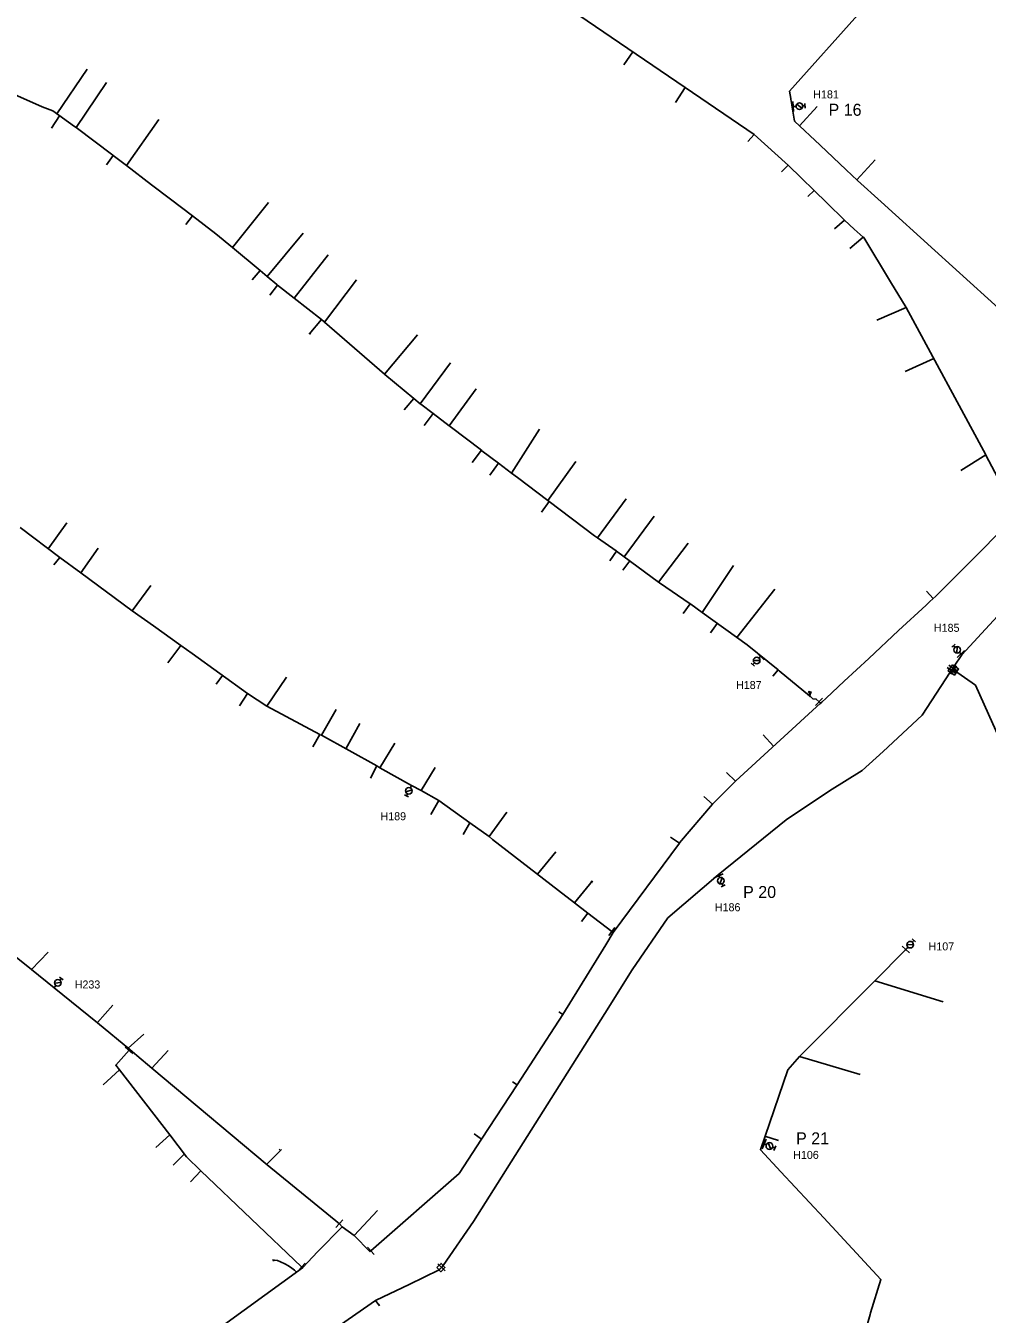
# Model space of a CAD drawing. Extents: x -548873 to -538270, y -1201997 to -1192514.
# Drawn here: x -544704.3 to -544463.9, y -1193277.9 to -1192955.8 of the extents above; entities that cross this region are included whole.
import ezdxf

# ---------------------------------------------------------------- set-up
doc = ezdxf.new("R2010")
doc.units = 0
for name, color, linetype in [('KN_HRAN_STÁTNÍ', 7, 'Continuous'), ('KN_PARC_Č', 7, 'Continuous'), ('KN_VKP_HRAN_SPORNÁ', 7, 'Continuous'), ('PK_PARC_Čv', 7, 'Continuous'), ('Vrstva 29', 7, 'Continuous'), ('Vrstva 39', 7, 'Continuous')]:
    doc.layers.add(name, color=color, linetype=linetype)

# ---------------------------------------------------------------- blocks, each defined once
blk = doc.blocks.new('160')
at = {"layer": 'KN_HRAN_STÁTNÍ'}
blk.add_circle((0, 0), 0.0458, dxfattribs=at)
blk = doc.blocks.new('147')
at = {"layer": 'KN_HRAN_STÁTNÍ'}
blk.add_line((0, 1.27), (0, -1.27), dxfattribs=at)
blk = doc.blocks.new('133')
at = {"layer": 'KN_HRAN_STÁTNÍ'}
for p, q in [((0.28, 0), (0, 0)), ((0.54, 0.58), (1.7, -0.58)), ((1.94, 0), (2.52, 0)), ((2.52, 0.58), (2.52, -0.58))]:
    blk.add_line(p, q, dxfattribs=at)
blk.add_circle((1.11, 0), 0.825, dxfattribs=at)
blk = doc.blocks.new('150')
at = {"layer": 'KN_HRAN_STÁTNÍ'}
blk.add_line((0, 1.27), (0, -1.27), dxfattribs=at)
blk = doc.blocks.new('128')
at = {"layer": 'KN_HRAN_STÁTNÍ'}
for p, q in [((-0.19, 1.06), (-0.43, 1.15)), ((-0.36, 0.84), (-0.19, 1.06)), ((-0.19, 1.06), (-0.02, 1.25)), ((-0.19, 1.06), (0, 0)), ((0.05, 0.95), (-0.19, 1.06)), ((-0.1, 1), (0.41, 0.91)), ((-0.07, 0.82), (0.17, 0.96)), ((0.17, 0.96), (-0.02, 1.13)), ((0.17, 0.96), (0, 0)), ((0.19, 1.21), (0.17, 0.96)), ((0.17, 0.96), (0.38, 1.08)), ((0.36, 0.77), (0.17, 0.96))]:
    blk.add_line(p, q, dxfattribs=at)

msp = doc.modelspace()

# ---------------------------------------------------------------- linework, layer by layer
at = {"layer": 'KN_PARC_Č'}
for points in [[(-544552.563, -1192962.313), (-544554.747, -1192965.528)], [(-544696.557, -1192977.763), (-544688.945, -1192966.668)], [(-544691.743, -1192981.23), (-544684.158, -1192969.979)], [(-544539.413, -1192971.242), (-544541.838, -1192974.939)], [(-544510.834, -1192980.776), (-544506.437, -1192975.971)], [(-544695.852, -1192978.269), (-544697.877, -1192981.372)], [(-544679.159, -1192990.721), (-544671.055, -1192979.195)], [(-544522.184, -1192982.942), (-544523.759, -1192984.755)], [(-544682.451, -1192988.202), (-544684.101, -1192990.568)], [(-544513.715, -1192990.627), (-544515.313, -1192992.312)], [(-544496.492, -1192994.312), (-544491.896, -1192989.278)], [(-544507.167, -1192997.006), (-544508.734, -1192998.469)], [(-544652.623, -1193011.242), (-544643.629, -1192999.931)], [(-544662.648, -1193003.313), (-544664.279, -1193005.439)], [(-544499.576, -1193004.409), (-544502.123, -1193006.532)], [(-544643.97, -1193018.447), (-544634.949, -1193007.651)], [(-544494.915, -1193008.609), (-544498.254, -1193011.44)], [(-544637.186, -1193023.891), (-544628.666, -1193013.022)], [(-544645.731, -1193016.98), (-544647.729, -1193019.337)], [(-544641.352, -1193020.618), (-544643.28, -1193023.111)], [(-544629.585, -1193029.871), (-544621.659, -1193019.321)], [(-544484.158, -1193026.242), (-544491.515, -1193029.421)], [(-544630.393, -1193029.228), (-544633.485, -1193032.887)], [(-544633.288, -1193032.654), (-544633.032, -1193032.902)], [(-544614.612, -1193042.888), (-544606.346, -1193033.069)], [(-544605.671, -1193050.288), (-544598.083, -1193040.009)], [(-544477.297, -1193038.937), (-544484.393, -1193042.193)], [(-544598.47, -1193055.78), (-544591.723, -1193046.565)], [(-544607.286, -1193048.952), (-544609.698, -1193051.761)], [(-544602.449, -1193052.749), (-544604.682, -1193055.69)], [(-544582.838, -1193067.588), (-544575.843, -1193056.6)], [(-544590.372, -1193061.918), (-544592.702, -1193064.947)], [(-544464.277, -1193063.025), (-544470.496, -1193066.929)], [(-544586.126, -1193065.113), (-544588.276, -1193068.114)], [(-544573.78, -1193074.441), (-544566.778, -1193064.72)], [(-544573.425, -1193074.71), (-544575.367, -1193077.389)], [(-544561.39, -1193083.781), (-544554.189, -1193074.057)], [(-544554.668, -1193088.533), (-544547.159, -1193078.388)], [(-544698.699, -1193086.56), (-544694.063, -1193080.04)], [(-544546.072, -1193094.881), (-544538.716, -1193085.135)], [(-544695.835, -1193088.729), (-544697.309, -1193090.56)], [(-544690.58, -1193092.58), (-544686.181, -1193086.351)], [(-544556.59, -1193087.113), (-544558.311, -1193089.543)], [(-544553.281, -1193089.557), (-544554.982, -1193091.91)], [(-544535.197, -1193102.446), (-544527.365, -1193090.684)], [(-544677.716, -1193102.007), (-544673.08, -1193095.702)], [(-544526.48, -1193108.739), (-544517.008, -1193096.655)], [(-544477.419, -1193098.937), (-544479.091, -1193097.135)], [(-544538.191, -1193100.29), (-544539.897, -1193102.69)], [(-544531.41, -1193105.18), (-544533.126, -1193107.544)], [(-544665.535, -1193110.695), (-544668.8, -1193115.028)], [(-544516.187, -1193116.808), (-544517.478, -1193118.393)], [(-544655.161, -1193118.17), (-544656.72, -1193120.413)], [(-544644.007, -1193125.875), (-544639.156, -1193118.593)], [(-544648.905, -1193122.676), (-544650.905, -1193125.814)], [(-544630.399, -1193133.154), (-544626.709, -1193126.717)], [(-544624.292, -1193136.532), (-544620.774, -1193130.171)], [(-544630.805, -1193132.932), (-544632.56, -1193136.071)], [(-544517.327, -1193135.896), (-544519.926, -1193133.051)], [(-544615.759, -1193141.252), (-544612.068, -1193135.091)], [(-544616.531, -1193140.825), (-544618.139, -1193143.839)], [(-544605.46, -1193146.987), (-544601.931, -1193141.209)], [(-544526.877, -1193144.631), (-544529.128, -1193142.424)], [(-544601.063, -1193149.437), (-544603.031, -1193152.984)], [(-544532.605, -1193150.374), (-544534.738, -1193148.484)], [(-544588.485, -1193158.492), (-544583.991, -1193152.368)], [(-544593.281, -1193155.037), (-544594.973, -1193157.975)], [(-544540.888, -1193160.119), (-544543.087, -1193158.62)], [(-544576.397, -1193167.831), (-544571.814, -1193162.282)], [(-544567.093, -1193175.016), (-544562.635, -1193169.556)], [(-544562.825, -1193169.788), (-544563.058, -1193169.6)], [(-544562.825, -1193169.788), (-544562.582, -1193169.964)], [(-544563.754, -1193177.595), (-544565.364, -1193179.732)], [(-544702.914, -1193191.718), (-544698.68, -1193187.35)], [(-544492.02, -1193194.514), (-544474.9, -1193199.779)], [(-544686.37, -1193204.994), (-544682.51, -1193200.6)], [(-544570.016, -1193202.943), (-544571.008, -1193202.272)], [(-544678.732, -1193211.393), (-544674.78, -1193207.83)], [(-544672.785, -1193216.375), (-544668.708, -1193211.976)], [(-544510.838, -1193213.431), (-544495.705, -1193217.946)], [(-544680.913, -1193216.779), (-544684.994, -1193220.504)], [(-544581.478, -1193220.511), (-544582.628, -1193219.787)], [(-544668.284, -1193233.013), (-544671.824, -1193236.195)], [(-544590.357, -1193234.131), (-544592.203, -1193232.784)], [(-544519.479, -1193233.391), (-544516.062, -1193234.492)], [(-544644.095, -1193240.409), (-544640.335, -1193236.721)], [(-544640.609, -1193236.99), (-544640.969, -1193236.58)], [(-544664.684, -1193237.838), (-544667.42, -1193240.634)], [(-544660.554, -1193241.995), (-544663.146, -1193244.767)], [(-544622.24, -1193258.16), (-544616.386, -1193251.924)], [(-544636.617, -1193267.35), (-544637.133, -1193266.878), (-544637.781, -1193266.336), (-544638.635, -1193265.787), (-544639.514, -1193265.268), (-544640.639, -1193264.742), (-544641.393, -1193264.484), (-544642.187, -1193264.325), (-544642.641, -1193264.278)], [(-544642.343, -1193264.309), (-544642.381, -1193264.607)], [(-544616.853, -1193274.488), (-544615.894, -1193275.746)], [(-544616.076, -1193275.507), (-544615.836, -1193275.327)]]:
    msp.add_lwpolyline(points, dxfattribs=at)
at = {"layer": 'KN_VKP_HRAN_SPORNÁ'}
for points in [[(-544560.275, -1192940.72), (-544559.97, -1192940.35), (-544557.033, -1192936.489), (-544556.428, -1192935.692), (-544545.966, -1192923.41), (-544534.516, -1192909.967), (-544533.273, -1192908.508), (-544530.926, -1192907.242), (-544528.833, -1192909.155), (-544521.348, -1192915.993), (-544512.949, -1192923.667), (-544498.441, -1192936.942), (-544491.038, -1192943.716), (-544490.115, -1192946.195), (-544495.563, -1192952.279), (-544513.363, -1192972.156), (-544513.04, -1192974.001), (-544513.001, -1192974.228), (-544512.946, -1192974.544), (-544512.868, -1192974.987), (-544512.752, -1192975.65), (-544512.058, -1192979.621)], [(-544456.83, -1193077.14), (-544464.218, -1193063.134), (-544464.277, -1193063.026), (-544484.158, -1193026.242), (-544488.072, -1193019.795), (-544494.802, -1193008.711), (-544494.915, -1193008.609), (-544497.144, -1193006.604), (-544499.581, -1193004.404), (-544504.015, -1193000.08), (-544513.635, -1192990.699), (-544522.182, -1192982.943), (-544539.415, -1192971.241), (-544566.053, -1192953.153), (-544568.615, -1192951.413)], [(-544508.241, -1193123.394), (-544508.346, -1193123.307), (-544515.91, -1193117.03), (-544516.187, -1193116.808), (-544523.93, -1193110.58), (-544535.197, -1193102.446), (-544538.06, -1193100.38), (-544538.191, -1193100.29), (-544545.83, -1193095.06), (-544546.072, -1193094.881), (-544556.59, -1193087.113), (-544556.73, -1193087.01), (-544561.39, -1193083.781), (-544562.07, -1193083.31), (-544573.425, -1193074.71), (-544573.78, -1193074.441), (-544581.36, -1193068.7), (-544582.838, -1193067.588), (-544586.126, -1193065.113), (-544590.25, -1193062.01), (-544590.372, -1193061.918), (-544598.221, -1193055.969), (-544598.47, -1193055.78), (-544602.449, -1193052.749), (-544605.56, -1193050.38), (-544605.671, -1193050.288), (-544607.286, -1193048.952), (-544614.54, -1193042.95), (-544614.628, -1193042.874), (-544629.585, -1193029.871), (-544629.689, -1193029.781), (-544630.393, -1193029.228), (-544637.186, -1193023.891), (-544641.352, -1193020.618), (-544641.541, -1193020.469), (-544643.97, -1193018.447), (-544645.731, -1193016.98), (-544652.623, -1193011.242), (-544656.794, -1193007.769), (-544662.648, -1193003.313), (-544668.152, -1192999.122), (-544672.87, -1192995.53), (-544679.159, -1192990.721), (-544682.451, -1192988.202), (-544682.52, -1192988.15), (-544691.743, -1192981.23), (-544692.13, -1192980.94), (-544697.55, -1192977.05), (-544700.25, -1192976.03), (-544709.386, -1192971.951)], [(-544439.522, -1193045.855), (-544447.584, -1193038.561), (-544454.922, -1193031.924), (-544476.979, -1193011.971), (-544490.412, -1192999.819), (-544496.321, -1192994.473), (-544499.196, -1192991.767), (-544505.659, -1192985.663), (-544512.058, -1192979.621)], [(-544422.078, -1193064.345), (-544430.27, -1193071.99), (-544441.63, -1193082.23), (-544453.43, -1193094.81), (-544470.28, -1193113.04), (-544472.153, -1193115.863), (-544472.455, -1193116.306)], [(-544456.45, -1193078.116), (-544462.553, -1193084.168), (-544464.285, -1193085.892), (-544471.685, -1193093.259), (-544475.202, -1193096.76), (-544476.79, -1193098.341), (-544478.25, -1193099.724), (-544479.197, -1193100.606), (-544486.066, -1193107.001), (-544493.541, -1193113.959), (-544499.639, -1193119.637), (-544504.217, -1193123.898), (-544505.249, -1193124.859), (-544505.577, -1193125.164)], [(-544705.725, -1193081.237), (-544695.839, -1193088.726), (-544690.581, -1193092.579), (-544677.721, -1193102.003), (-544672.419, -1193105.785), (-544665.535, -1193110.695), (-544662.739, -1193112.71), (-544648.907, -1193122.675), (-544644.007, -1193125.875), (-544630.805, -1193132.932), (-544630.668, -1193133.005), (-544630.399, -1193133.154), (-544616.529, -1193140.826), (-544615.761, -1193141.251), (-544607.831, -1193145.667), (-544605.462, -1193146.987), (-544601.063, -1193149.437), (-544601.015, -1193149.463), (-544593.281, -1193155.037), (-544588.481, -1193158.495), (-544587.585, -1193159.187), (-544571.081, -1193171.939), (-544567.093, -1193175.016), (-544563.755, -1193177.594), (-544557.758, -1193182.227)], [(-544472.889, -1193116.942), (-544473.188, -1193117.38), (-544480.16, -1193128.16), (-544489.91, -1193137.19), (-544495.19, -1193141.96), (-544503.33, -1193147.04), (-544514.15, -1193154.28), (-544531.2, -1193168.08), (-544543.76, -1193178.79), (-544552.71, -1193191.79), (-544559.541, -1193202.681), (-544592.365, -1193254.676), (-544599.934, -1193265.732), (-544600.353, -1193266.159)], [(-544472.647, -1193116.587), (-544472.889, -1193116.942)], [(-544472.455, -1193116.306), (-544472.647, -1193116.587)], [(-544472.647, -1193116.587), (-544472.301, -1193116.827)], [(-544472.301, -1193116.827), (-544466.87, -1193120.59), (-544451.28, -1193155.4), (-544438.81, -1193184.53), (-544426.952, -1193204.028), (-544419.053, -1193215.611)], [(-544505.94, -1193124.82), (-544506.68, -1193124.12), (-544507.49, -1193124.01), (-544508.121, -1193123.493), (-544508.21, -1193123.42), (-544508.241, -1193123.394)], [(-544505.577, -1193125.164), (-544526.747, -1193144.501), (-544532.543, -1193150.301), (-544532.605, -1193150.374), (-544540.851, -1193160.07), (-544540.888, -1193160.119), (-544557.446, -1193182.468)], [(-544505.577, -1193125.164), (-544505.94, -1193124.82)], [(-544747.243, -1193152.968), (-544742.767, -1193157.412), (-544724.83, -1193174.13), (-544721.659, -1193176.674), (-544711.014, -1193185.218), (-544702.912, -1193191.719), (-544697.238, -1193196.274), (-544686.354, -1193205.008), (-544678.333, -1193211.727)], [(-544557.446, -1193182.468), (-544559.302, -1193185.547), (-544570.017, -1193202.946), (-544577.31, -1193214.123), (-544581.479, -1193220.512), (-544590.357, -1193234.131), (-544595.954, -1193242.716), (-544618.055, -1193262.022)], [(-544557.758, -1193182.227), (-544557.446, -1193182.468)], [(-544484.41, -1193186.865), (-544484.5, -1193186.955), (-544492.023, -1193194.518), (-544510.839, -1193213.432), (-544513.794, -1193216.753), (-544519.47, -1193233.363), (-544520.63, -1193236.758), (-544515.481, -1193242.28), (-544504.791, -1193253.747), (-544490.482, -1193269.207), (-544493.088, -1193277.551), (-544493.202, -1193277.955), (-544495.843, -1193287.359), (-544487.234, -1193305.248), (-544486.992, -1193305.75), (-544481.617, -1193311.689), (-544453.414, -1193322.024), (-544452.85, -1193322.231), (-544437.022, -1193308.689), (-544436.391, -1193308.88)], [(-544678.48, -1193211.89), (-544681.831, -1193215.599), (-544680.913, -1193216.779), (-544668.284, -1193233.013), (-544664.139, -1193238.569), (-544660.554, -1193241.995), (-544635.36, -1193266.07)], [(-544678.333, -1193211.727), (-544678.48, -1193211.89)], [(-544678.333, -1193211.727), (-544676.553, -1193213.218), (-544672.784, -1193216.376), (-544661.467, -1193225.856), (-544643.99, -1193240.497), (-544625.9, -1193255.25)], [(-544625.17, -1193256.07), (-544631.25, -1193262.16), (-544635.144, -1193266.278)], [(-544625.9, -1193255.25), (-544625.17, -1193256.07)], [(-544618.055, -1193262.022), (-544618.281, -1193262.219), (-544622.24, -1193258.16), (-544625.17, -1193256.07)], [(-544635.36, -1193266.07), (-544635.144, -1193266.278)], [(-544600.353, -1193266.159), (-544600.704, -1193266.516)], [(-544635.144, -1193266.278), (-544659.112, -1193283.727), (-544667.892, -1193289.812), (-544673.961, -1193293.991), (-544683.581, -1193300.981)], [(-544600.704, -1193266.516), (-544600.983, -1193266.801), (-544608.484, -1193270.417), (-544616.683, -1193274.37), (-544616.853, -1193274.488), (-544639.019, -1193289.905), (-544657.955, -1193302.649), (-544673.656, -1193314.224), (-544673.86, -1193314.379)]]:
    msp.add_lwpolyline(points, dxfattribs=at)
at = {"layer": 'PK_PARC_Čv'}
for points in [[(-544512.691, -1192976), (-544511.997, -1192975.961)], [(-544520.507, -1193113.333), (-544520.8, -1193113.64)], [(-544470.28, -1193113.04), (-544470.52, -1193112.8), (-544470.68, -1193112.62)], [(-544472.625, -1193115.547), (-544471.09, -1193116.576), (-544472.125, -1193118.093), (-544473.66, -1193117.064), (-544472.625, -1193115.547)], [(-544607.831, -1193145.667), (-544608.02, -1193146.05)], [(-544531.2, -1193168.08), (-544531.06, -1193168.28), (-544530.97, -1193168.49)], [(-544484.41, -1193186.865), (-544484.263, -1193186.717), (-544483.933, -1193186.338)], [(-544697.238, -1193196.274), (-544696.97, -1193195.94)], [(-544520.098, -1193235.201), (-544519.666, -1193235.328), (-544519.428, -1193235.398)], [(-544601.5, -1193266.23), (-544600.45, -1193265.16), (-544599.52, -1193266.19), (-544600.57, -1193267.26), (-544601.5, -1193266.23)]]:
    msp.add_lwpolyline(points, dxfattribs=at)

# ---------------------------------------------------------------- block references
for name, p, xscale, yscale, rotation in [('150', (-544512.467, -1192975.987), 1.0000000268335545, 1.0000000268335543, 3.9999997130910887), ('133', (-544511.997, -1192975.961), 1.0000000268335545, 1.0000000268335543, 3.9999997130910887), ('133', (-544470.68, -1193112.62), 1.0000000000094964, 1.0000000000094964, 132.0000013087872), ('133', (-544520.8, -1193113.64), 1.00000000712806, 1.00000000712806, -133.00000056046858), ('150', (-544520.577, -1193113.406), 1.00000000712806, 1.00000000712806, 46.99999943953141), ('150', (-544470.52, -1193112.8), 1.0000000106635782, 1.0000000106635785, -45.99999834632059), ('133', (-544608.02, -1193146.05), 1.0000000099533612, 1.0000000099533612, -116.000000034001), ('150', (-544531.06, -1193168.28), 0.9999999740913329, 0.9999999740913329, -65.99999939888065), ('133', (-544530.97, -1193168.49), 0.9999999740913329, 0.9999999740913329, -65.99999939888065), ('133', (-544483.933, -1193186.338), 1.0000000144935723, 1.0000000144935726, 49.00000089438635), ('150', (-544484.263, -1193186.717), 1.0000000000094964, 1.0000000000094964, 47.99999869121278), ('133', (-544696.97, -1193195.94), 1.000000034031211, 1.0000000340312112, 51.999999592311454), ('150', (-544519.666, -1193235.328), 1.0365458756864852, 1.0365458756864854, -21.97149085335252), ('133', (-544519.428, -1193235.398), 1.0365458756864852, 1.0365458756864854, -21.97149085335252)]:
    msp.add_blockref(name, p, dxfattribs=dict(at, xscale=xscale, yscale=yscale, rotation=rotation))
at = {"layer": 'Vrstva 29'}
for name, p, xscale, yscale, rotation in [('160', (-544512.058, -1192979.621), 1.0000000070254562, 1.0000000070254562, 118.99999892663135), ('147', (-544472.889, -1193116.942), 0.9999999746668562, 0.999999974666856, -124.00000045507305), ('147', (-544472.455, -1193116.306), 0.9999999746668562, 0.999999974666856, -124.00000045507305), ('147', (-544472.301, -1193116.827), 0.9999999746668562, 0.999999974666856, 145.99999954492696), ('160', (-544472.647, -1193116.587), 1.0060666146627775, 1.0060666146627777, -167.3452647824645), ('160', (-544508.241, -1193123.394), 1.000000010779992, 1.0000000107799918, -38.9999989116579), ('147', (-544505.94, -1193124.82), 1.00000000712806, 1.00000000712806, 136.99999943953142), ('160', (-544505.577, -1193125.164), 1.00000000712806, 1.00000000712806, -136.99999943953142), ('147', (-544557.758, -1193182.227), 0.9999999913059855, 0.9999999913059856, 142.99999806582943), ('160', (-544557.446, -1193182.468), 0.9999999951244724, 0.9999999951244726, -123.00000127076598), ('160', (-544484.41, -1193186.865), 1.0000000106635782, 1.0000000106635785, -134.00000165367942), ('147', (-544678.48, -1193211.89), 1.0000000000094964, 1.0000000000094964, -132.0000013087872), ('160', (-544678.333, -1193211.727), 1.000000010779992, 1.0000000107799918, -38.9999989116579), ('147', (-544625.9, -1193255.25), 1.00000000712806, 1.00000000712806, -43.0000005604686), ('160', (-544625.17, -1193256.07), 1.0018265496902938, 1.0018265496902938, 6.078126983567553), ('147', (-544618.055, -1193262.022), 1.0000000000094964, 1.0000000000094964, 42.000001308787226), ('147', (-544635.36, -1193266.07), 1.00000000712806, 1.00000000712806, 136.99999943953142), ('160', (-544635.144, -1193266.278), 1.0000000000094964, 1.0000000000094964, 42.000001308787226), ('147', (-544600.353, -1193266.159), 1.0000000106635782, 1.0000000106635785, -134.00000165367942), ('160', (-544600.704, -1193266.516), 1.0000000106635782, 1.0000000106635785, 45.99999834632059)]:
    msp.add_blockref(name, p, dxfattribs=dict(at, xscale=xscale, yscale=yscale, rotation=rotation))
at = {"layer": 'Vrstva 39'}
msp.add_blockref('128', (-544508.241, -1193123.394), dxfattribs=at)

# ---------------------------------------------------------------- texts
at = {"layer": 'PK_PARC_Čv'}
for s, height, p in [('H181', 2, (-544507.407, -1192973.941)), ('P 16', 3, (-544503.587, -1192978.281)), ('H185', 2, (-544477.24, -1193107.29)), ('H187', 2, (-544526.72, -1193121.58)), ('H189', 2, (-544615.62, -1193154.39)), ('P 20', 3, (-544524.95, -1193173.83)), ('H186', 2, (-544532.01, -1193177.14)), ('H107', 2, (-544478.563, -1193186.928)), ('H233', 2, (-544692.08, -1193196.45)), ('P 21', 3, (-544511.708, -1193235.418)), ('H106', 2, (-544512.428, -1193239.048))]:
    msp.add_text(s, height=height, dxfattribs=at).set_placement(p)

doc.saveas('drawing.dxf')
